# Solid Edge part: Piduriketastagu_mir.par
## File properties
Author: Türk
Template: Iso Part.par
Last saved by: Türk
Revision: 3
Application: Solid Edge
Accuracy: 0,990
Username: Türk
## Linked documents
Piduriketastagu.par
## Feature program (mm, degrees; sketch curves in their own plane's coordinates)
part copy "CopiedPart_1"
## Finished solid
Body 1: solid body, 367 faces, 930 edges, 578 vertices.
  Faces by surface: plane 206, swept 68, cone 35, spline 34, cylinder 24
  Edges by curve: line 374, circle 250, spline 170, intersection 102, curve on surface 34
Bounding box of the edges (mm; curved faces can reach further): 260.000 x 30.000 x 260.000, from (-130, -15, -130) to (130, 15, 130).
Cylindrical faces by radius (mm): R6 x5, R62.1667 x17, R62.5 x1, R130 x1
Conical faces (half-angle, radius in mm at the cone's reference point): 18.4349 deg R57.5 x1, 45 deg R129 x17, 45 deg R130 x17
Planar faces by outward normal: +y 69, -y 52, oblique 85
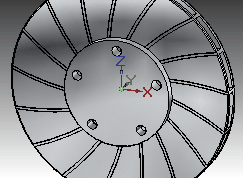
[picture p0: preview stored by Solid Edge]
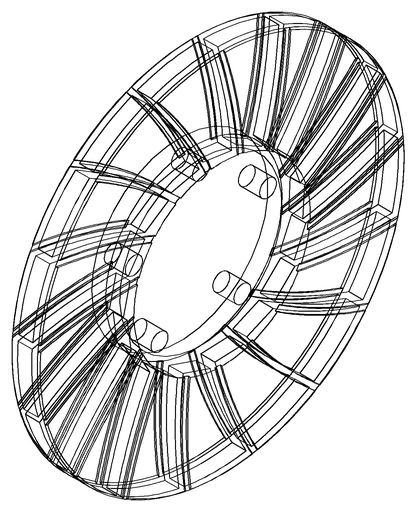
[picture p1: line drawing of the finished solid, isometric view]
